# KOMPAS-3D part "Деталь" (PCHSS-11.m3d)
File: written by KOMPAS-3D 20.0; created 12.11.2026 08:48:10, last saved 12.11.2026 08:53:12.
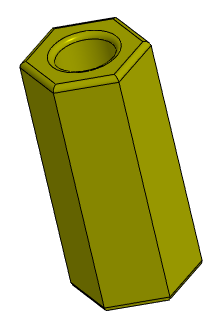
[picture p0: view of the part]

Document properties: Полное имя файла: D:\myProjects\Progect_esp32\box_compas\прочее\PCHSS-11.m3d

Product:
- Part/product: Деталь
    Масса: 0.00115433

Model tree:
1. Эскиз:1
2. Элемент выдавливания:1
     Расстояние 1 = 11
3. Эскиз:2  (with: Элемент выдавливания:1)
4. Элемент выдавливания:2
     Расстояние 2 = 11
5. Скругление:1  (with: Элемент выдавливания:1)
     Радиус = 0.25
